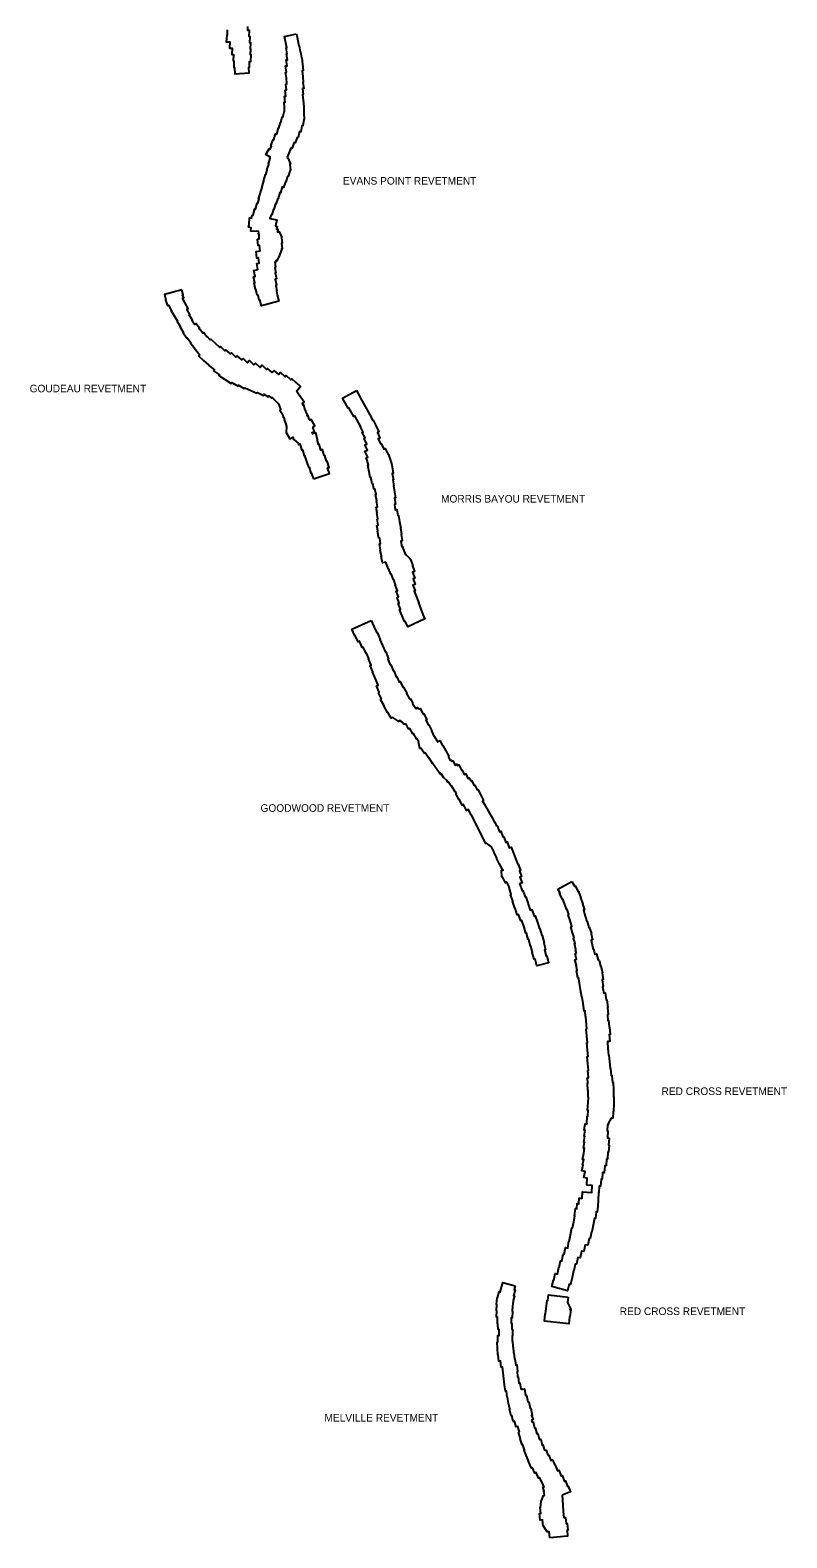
# Model space of a CAD drawing. Extents: x 2650582 to 3923188, y 277893 to 989177.
# Drawn here: x 3143470 to 3159448, y 789511 to 821343 of the extents above; entities that cross this region are included whole.
import ezdxf

# ---------------------------------------------------------------- set-up
doc = ezdxf.new("R2010")
doc.units = 0
doc.layers.add('Level 3', color=7, linetype='Continuous')

msp = doc.modelspace()

# ---------------------------------------------------------------- linework, layer by layer
at = {"layer": 'Level 3'}
for points in [[(3147633, 821352), (3147629, 821238), (3147622, 821239), (3147612, 821099), (3147689, 821094), (3147680, 820964), (3147736, 820960), (3147727, 820830), (3147764, 820828), (3147760, 820694), (3147771, 820693), (3147773, 820558), (3147782, 820558), (3147789, 820424), (3148096, 820440), (3148090, 820564), (3148104, 820564), (3148102, 820682), (3148131, 820681), (3148136, 820821), (3148122, 820821), (3148130, 820942), (3148121, 820943), (3148130, 821073), (3148106, 821074), (3148115, 821204), (3148095, 821206), (3148099, 821335), (3148068, 821336), (3148067, 821422)], [(3148841, 819616), (3148838, 819714), (3148831, 819822), (3148852, 819823), (3148839, 819946), (3148872, 819950), (3148857, 820078), (3148882, 820081), (3148868, 820206), (3148890, 820209), (3148880, 820336), (3148863, 820449), (3148885, 820453), (3148865, 820588), (3148895, 820593), (3148879, 820716), (3148904, 820719), (3148885, 820842), (3148897, 820844), (3148877, 820970), (3148889, 820972), (3148840, 821211), (3149093, 821264)], [(3149093, 821264), (3149145, 821013), (3149153, 821014), (3149173, 820885), (3149179, 820886), (3149199, 820758), (3149205, 820759), (3149223, 820623), (3149219, 820622), (3149238, 820490), (3149214, 820487), (3149231, 820366), (3149226, 820365), (3149236, 820238), (3149231, 820238), (3149246, 820111), (3149224, 820108), (3149238, 819982), (3149223, 819980), (3149236, 819866), (3149246, 819729), (3149248, 819729), (3149251, 819587), (3149253, 819455), (3149247, 819455), (3149228, 819322), (3149210, 819324), (3149184, 819196), (3149157, 819201), (3149126, 819075), (3149106, 819080), (3149069, 818961), (3149044, 818969), (3148996, 818845), (3148973, 818854), (3148929, 818746), (3148932, 818745), (3148894, 818664)], [(3148449, 818289), (3148476, 818389), (3148471, 818391), (3148508, 818510), (3148500, 818512), (3148537, 818641), (3148530, 818644), (3148535, 818663), (3148448, 818715), (3148520, 818834), (3148533, 818826), (3148563, 818890), (3148549, 818896), (3148605, 819032), (3148617, 819028), (3148652, 819154), (3148678, 819147), (3148715, 819279), (3148720, 819277), (3148754, 819394), (3148760, 819392), (3148794, 819510), (3148803, 819508), (3148837, 819618), (3148841, 819616)], [(3148894, 818664), (3148904, 818642), (3148910, 818644), (3148969, 818517), (3148955, 818511), (3148969, 818388), (3148960, 818387), (3148918, 818251), (3148903, 818256), (3148871, 818138), (3148859, 818142)], [(3148300, 817091), (3148131, 817098), (3148134, 817166), (3148081, 817182), (3148096, 817231), (3148105, 817379), (3148142, 817377), (3148161, 817440), (3148176, 817435), (3148216, 817571), (3148231, 817566), (3148266, 817690), (3148275, 817687), (3148303, 817780), (3148295, 817782), (3148369, 818022), (3148364, 818023), (3148402, 818153), (3148397, 818154), (3148439, 818292), (3148449, 818289)], [(3148859, 818142), (3148822, 818023), (3148794, 818032), (3148758, 817909), (3148743, 817913), (3148705, 817790), (3148697, 817792), (3148659, 817669), (3148648, 817673), (3148614, 817561), (3148608, 817563), (3148574, 817441), (3148557, 817445), (3148534, 817367), (3148679, 817336)], [(3148679, 817336), (3148650, 817204), (3148684, 817196), (3148671, 817142), (3148701, 817138), (3148695, 817079), (3148721, 817094), (3148788, 816970), (3148778, 816965), (3148791, 816848), (3148775, 816846), (3148790, 816729), (3148776, 816727), (3148786, 816723), (3148736, 816592), (3148736, 816592), (3148678, 816474), (3148661, 816483), (3148665, 816450), (3148634, 816446), (3148652, 816336), (3148636, 816333), (3148658, 816221), (3148645, 816218), (3148671, 816090), (3148645, 816085), (3148670, 815958), (3148655, 815955), (3148682, 815842), (3148674, 815840), (3148689, 815753), (3148689, 815753), (3148723, 815618), (3148353, 815524), (3148321, 815648), (3148305, 815645), (3148288, 815750), (3148266, 815745), (3148236, 815872), (3148225, 815870), (3148198, 816007), (3148214, 816010), (3148189, 816137), (3148219, 816143), (3148193, 816272), (3148276, 816288), (3148255, 816413), (3148308, 816422), (3148294, 816535), (3148258, 816530), (3148241, 816669), (3148329, 816681), (3148314, 816796), (3148287, 816793), (3148271, 816932), (3148306, 816936), (3148304, 817038), (3148295, 817039), (3148300, 817091)], [(3146676, 815862), (3146304, 815763), (3146335, 815647), (3146327, 815644), (3146369, 815527), (3146388, 815534), (3146453, 815417), (3146450, 815415), (3146583, 815196), (3146577, 815191), (3146645, 815078), (3146639, 815074), (3146711, 814961), (3146698, 814952), (3146781, 814838), (3146789, 814844), (3146864, 814745), (3146855, 814737), (3146934, 814640), (3146930, 814636), (3147018, 814533), (3147012, 814527), (3147052, 814489)], [(3147036, 815039), (3147035, 815040), (3147048, 815051), (3146969, 815153), (3146937, 815129), (3146885, 815212), (3146896, 815219), (3146830, 815331), (3146845, 815340), (3146778, 815452), (3146807, 815469), (3146741, 815576), (3146744, 815578), (3146684, 815685), (3146712, 815695), (3146690, 815754), (3146704, 815758), (3146676, 815862)], [(3149095, 813723), (3149181, 813823), (3149092, 813900), (3149086, 813894), (3148995, 813981), (3148976, 813962), (3148879, 814052), (3148853, 814024), (3148756, 814112), (3148719, 814070), (3148622, 814160), (3148580, 814114), (3148484, 814203), (3148462, 814179), (3148366, 814267), (3148326, 814223), (3148230, 814313), (3148196, 814277), (3148103, 814365), (3148061, 814322), (3147965, 814410), (3147937, 814380), (3147840, 814469), (3147814, 814441), (3147719, 814530), (3147699, 814509), (3147605, 814597), (3147583, 814572), (3147486, 814661), (3147472, 814646), (3147287, 814819), (3147272, 814804), (3147210, 814876), (3147200, 814868), (3147127, 814958), (3147114, 814947), (3147041, 815043), (3147036, 815039)], [(3147052, 814489), (3147029, 814461), (3147133, 814370), (3147130, 814366), (3147245, 814269), (3147243, 814266), (3147360, 814173), (3147344, 814149), (3147466, 814066), (3147456, 814051), (3147713, 813882), (3147727, 813904), (3147859, 813830), (3147867, 813845), (3147992, 813778), (3148000, 813794), (3148260, 813677), (3148268, 813696), (3148396, 813633), (3148407, 813655), (3148499, 813601), (3148512, 813623), (3148563, 813574), (3148576, 813586), (3148596, 813572), (3148672, 813499), (3148712, 813456), (3148713, 813456), (3148758, 813344), (3148758, 813344), (3148762, 813334), (3148740, 813318), (3148799, 813235), (3148816, 813170), (3148825, 813172), (3148841, 813116)], [(3149450, 811869), (3149788, 811985), (3149748, 812100), (3149782, 812111), (3149741, 812245), (3149730, 812241), (3149692, 812366), (3149678, 812361), (3149640, 812486), (3149611, 812477), (3149573, 812601), (3149561, 812597), (3149529, 812703), (3149539, 812706), (3149502, 812841), (3149429, 812821), (3149422, 812850), (3149476, 812874), (3149442, 812949), (3149451, 812952), (3149446, 812972), (3149478, 812988), (3149407, 813123), (3149375, 813106), (3149361, 813133), (3149344, 813197), (3149328, 813193), (3149316, 813215), (3149324, 813219), (3149301, 813263), (3149288, 813312), (3149280, 813310), (3149247, 813430), (3149236, 813427), (3149224, 813465), (3149258, 813489), (3149167, 813619), (3149165, 813617), (3149095, 813723)], [(3150982, 810108), (3150909, 810095), (3150884, 810236), (3150886, 810237), (3150863, 810367), (3150871, 810369), (3150849, 810499), (3150871, 810502), (3150853, 810619), (3150833, 810615), (3150807, 810768), (3150810, 810769), (3150789, 810887), (3150817, 810892), (3150795, 811021), (3150810, 811023), (3150789, 811152), (3150800, 811154), (3150779, 811274), (3150805, 811279), (3150783, 811407), (3150787, 811408), (3150765, 811536), (3150773, 811537), (3150750, 811657), (3150729, 811654), (3150709, 811772), (3150689, 811768), (3150664, 811902), (3150648, 811899), (3150626, 812020), (3150628, 812020), (3150599, 812158), (3150615, 812161), (3150587, 812256), (3150562, 812308), (3150597, 812326), (3150538, 812452), (3150590, 812477), (3150538, 812586), (3150578, 812605), (3150522, 812723), (3150541, 812733), (3150483, 812849), (3150501, 812858), (3150444, 812967), (3150451, 812970), (3150325, 813198), (3150302, 813185), (3150198, 813370), (3150184, 813362), (3150067, 813575), (3150360, 813736)], [(3150360, 813736), (3150476, 813524), (3150472, 813522), (3150643, 813218), (3150645, 813218), (3150708, 813103), (3150715, 813107), (3150779, 812983), (3150774, 812980), (3150832, 812861), (3150802, 812846), (3150857, 812730), (3150822, 812713), (3150871, 812608), (3150885, 812615), (3150940, 812497), (3150966, 812510), (3151029, 812384), (3151039, 812387), (3151076, 812258), (3151086, 812260), (3151115, 812122), (3151113, 812121), (3151138, 811990), (3151117, 811986), (3151142, 811851), (3151126, 811848), (3151147, 811722), (3151142, 811721), (3151166, 811594), (3151161, 811594), (3151183, 811466), (3151163, 811462), (3151185, 811334), (3151160, 811330), (3151180, 811215), (3151213, 811221), (3151233, 811094), (3151245, 811096), (3151267, 810968), (3151271, 810969), (3151295, 810829), (3151290, 810828), (3151312, 810697), (3151305, 810696), (3151325, 810568), (3151323, 810568)], [(3148841, 813116), (3148832, 813111), (3148853, 813071), (3148858, 813052), (3148861, 813053), (3148883, 812972), (3148874, 812850), (3148879, 812850), (3148951, 812712), (3149017, 812747), (3149029, 812704), (3149037, 812706), (3149035, 812704), (3149129, 812622), (3149136, 812598), (3149166, 812606), (3149205, 812478), (3149219, 812482), (3149257, 812358), (3149265, 812361), (3149303, 812236), (3149308, 812238), (3149346, 812113), (3149360, 812118), (3149398, 811993), (3149407, 811996), (3149450, 811869)], [(3151323, 810568), (3151325, 810559), (3151300, 810555), (3151320, 810437), (3151335, 810440), (3151346, 810389), (3151394, 810265), (3151404, 810275), (3151498, 810171), (3151493, 810166), (3151502, 810170), (3151553, 810039), (3151543, 810035), (3151589, 809914), (3151546, 809897), (3151593, 809776), (3151556, 809762), (3151602, 809642), (3151554, 809623), (3151600, 809503), (3151581, 809496), (3151674, 809253), (3151670, 809251), (3151713, 809138), (3151715, 809139), (3151765, 809008), (3151760, 809006), (3151803, 808913), (3151444, 808748), (3151390, 808864), (3151374, 808858), (3151327, 808981), (3151323, 808979), (3151272, 809110), (3151289, 809117), (3151242, 809238), (3151263, 809247), (3151217, 809368), (3151247, 809380), (3151201, 809498), (3151227, 809508), (3151179, 809631), (3151188, 809634), (3151146, 809742), (3151142, 809741), (3151095, 809862), (3151085, 809858), (3151037, 809979), (3151033, 809977), (3150982, 810108)], [(3151402, 806705), (3151389, 806686), (3151374, 806696), (3151358, 806688), (3151343, 806718), (3151268, 806769), (3151252, 806745), (3151125, 806833), (3151096, 806817), (3151023, 806940), (3151018, 806937), (3150939, 807075), (3150944, 807078), (3150871, 807211), (3150892, 807222), (3150824, 807355), (3150841, 807364), (3150780, 807501), (3150817, 807517), (3150762, 807647), (3150759, 807646), (3150700, 807792), (3150705, 807794), (3150653, 807929), (3150669, 807935), (3150613, 808072), (3150619, 808075), (3150570, 808186), (3150563, 808183), (3150503, 808317), (3150482, 808308), (3150421, 808442), (3150397, 808430), (3150336, 808564), (3150324, 808558), (3150264, 808697), (3150671, 808876)], [(3150671, 808876), (3150727, 808749), (3150729, 808750), (3150789, 808620), (3150799, 808624), (3150864, 808480), (3150851, 808475), (3150908, 808349), (3150911, 808351), (3150971, 808213), (3150979, 808217), (3151038, 808072), (3151022, 808065), (3151071, 807940), (3151085, 807946), (3151139, 807810), (3151146, 807813), (3151199, 807688), (3151210, 807693), (3151262, 807578), (3151281, 807588), (3151342, 807469), (3151352, 807475), (3151424, 807344), (3151416, 807339), (3151481, 807226), (3151495, 807234), (3151554, 807134), (3151547, 807129), (3151612, 807021), (3151652, 807044), (3151674, 807006)], [(3151674, 807006), (3151706, 807023), (3151766, 806903), (3151783, 806912), (3151846, 806788), (3151824, 806778), (3151879, 806669), (3151890, 806674)], [(3151675, 806315), (3151633, 806384), (3151631, 806383), (3151564, 806494), (3151552, 806487), (3151485, 806598), (3151474, 806591), (3151469, 806599), (3151458, 806593), (3151402, 806705)], [(3151890, 806674), (3151952, 806549), (3151948, 806547), (3151976, 806486)], [(3152454, 805268), (3152442, 805261), (3152365, 805386), (3152358, 805382), (3152300, 805474), (3152290, 805467), (3152269, 805500), (3152204, 805558), (3152154, 805635), (3152139, 805628), (3152120, 805665), (3152112, 805659), (3151967, 805864), (3151965, 805863), (3151887, 805984), (3151880, 805979), (3151809, 806088), (3151789, 806075), (3151719, 806182), (3151699, 806177), (3151669, 806314), (3151675, 806315)], [(3151976, 806486), (3151990, 806463), (3151987, 806461), (3152049, 806359), (3152047, 806358), (3152072, 806318), (3152118, 806345), (3152179, 806239), (3152182, 806241), (3152310, 806018), (3152294, 806009)], [(3152294, 806009), (3152339, 805920), (3152364, 805932), (3152376, 805905), (3152396, 805915), (3152441, 805826), (3152481, 805845), (3152494, 805818), (3152520, 805832), (3152581, 805717), (3152590, 805721), (3152638, 805629), (3152667, 805643), (3152715, 805545), (3152737, 805558), (3152776, 805490)], [(3152776, 805490), (3152790, 805498), (3152844, 805398), (3152857, 805404), (3152911, 805303), (3152921, 805308), (3152976, 805202), (3152980, 805204), (3153045, 805077), (3153023, 805066), (3153056, 805005)], [(3153267, 803991), (3153212, 804100), (3153105, 804178), (3153092, 804171), (3152912, 804530), (3152911, 804530), (3152790, 804773), (3152784, 804770), (3152724, 804892), (3152685, 804871), (3152623, 804991), (3152595, 804977), (3152534, 805098), (3152526, 805094), (3152461, 805219), (3152475, 805226), (3152454, 805268)], [(3153056, 805005), (3153058, 805006), (3153202, 804745), (3153211, 804749), (3153276, 804617), (3153280, 804619), (3153319, 804537)], [(3153319, 804537), (3153333, 804542), (3153378, 804420), (3153409, 804431), (3153453, 804309), (3153469, 804315), (3153513, 804192), (3153543, 804203), (3153587, 804081), (3153628, 804096), (3153676, 803964), (3153675, 803964), (3153716, 803851), (3153721, 803853), (3153766, 803731), (3153775, 803735), (3153823, 803603), (3153802, 803595), (3153846, 803473), (3153813, 803461), (3153861, 803343), (3153802, 803320)], [(3153592, 803243), (3153534, 803357), (3153507, 803343), (3153446, 803465), (3153429, 803465), (3153424, 803606), (3153461, 803607), (3153454, 803622), (3153447, 803618), (3153388, 803734), (3153384, 803732), (3153317, 803864), (3153325, 803868), (3153262, 803988), (3153267, 803991)], [(3153802, 803320), (3153806, 803311), (3153809, 803312), (3153861, 803174), (3153873, 803178), (3153920, 803042), (3153935, 803047), (3154028, 802766), (3154061, 802778), (3154110, 802637), (3154132, 802645), (3154181, 802504), (3154186, 802505), (3154226, 802366), (3154233, 802368), (3154275, 802226), (3154281, 802227), (3154322, 802075), (3154315, 802073), (3154350, 801930), (3154334, 801926), (3154369, 801794), (3154378, 801796), (3154417, 801651), (3154172, 801585), (3154132, 801732), (3154110, 801726), (3154073, 801868), (3154075, 801868), (3154042, 802001), (3154036, 801999), (3153998, 802144), (3153989, 802142), (3153948, 802281), (3153938, 802278), (3153901, 802406), (3153900, 802406), (3153852, 802545), (3153829, 802538), (3153781, 802675), (3153757, 802668), (3153710, 802808), (3153705, 802806), (3153656, 802955), (3153662, 802957), (3153616, 803089), (3153628, 803094), (3153582, 803240), (3153592, 803243)], [(3155004, 801846), (3154987, 801929), (3154991, 801930), (3154964, 802057), (3154975, 802060), (3154945, 802180), (3154959, 802183), (3154925, 802288), (3154925, 802288), (3154885, 802412), (3154911, 802420), (3154871, 802544), (3154871, 802544), (3154831, 802668), (3154843, 802672), (3154810, 802774), (3154800, 802770), (3154750, 802901), (3154756, 802903), (3154720, 802997), (3154708, 802991), (3154651, 803119), (3154662, 803124), (3154615, 803210), (3154908, 803372)], [(3154908, 803372), (3154970, 803261), (3154988, 803269), (3155041, 803152), (3155048, 803154), (3155098, 803024), (3155091, 803021), (3155137, 802899), (3155131, 802897), (3155173, 802768), (3155152, 802761), (3155192, 802638), (3155187, 802636), (3155224, 802522), (3155230, 802524), (3155270, 802400), (3155277, 802402), (3155320, 802269), (3155314, 802267), (3155347, 802136), (3155319, 802128), (3155347, 801996), (3155345, 801995), (3155357, 801936)], [(3155357, 801936), (3155365, 801938), (3155378, 801888), (3155379, 801888), (3155384, 801863), (3155392, 801834), (3155426, 801843), (3155464, 801707), (3155484, 801711), (3155512, 801583), (3155523, 801586), (3155553, 801437), (3155549, 801437), (3155572, 801298), (3155549, 801294), (3155571, 801149), (3155558, 801147), (3155581, 801012), (3155609, 801017), (3155632, 800870), (3155647, 800872), (3155671, 800708), (3155662, 800706), (3155674, 800559), (3155658, 800557), (3155668, 800437), (3155682, 800438), (3155694, 800295)], [(3155226, 800254), (3155202, 800521), (3155198, 800521), (3155189, 800636), (3155169, 800633), (3155145, 800794), (3155125, 800929), (3155120, 800928), (3155094, 801079), (3155071, 801224), (3155052, 801339), (3155036, 801336), (3155007, 801484), (3155023, 801487), (3154997, 801602), (3155004, 801604), (3154973, 801717), (3155004, 801726), (3154975, 801838), (3155004, 801846)], [(3155694, 800295), (3155701, 800296), (3155715, 800139), (3155695, 800137), (3155707, 799992), (3155658, 799988), (3155671, 799844), (3155667, 799843), (3155680, 799704), (3155689, 799705), (3155702, 799566), (3155703, 799566), (3155717, 799419), (3155725, 799420), (3155738, 799272), (3155753, 799274), (3155767, 799122), (3155782, 799123), (3155786, 798972), (3155790, 798972), (3155789, 798822), (3155796, 798821), (3155793, 798673), (3155796, 798673), (3155788, 798515), (3155779, 798515), (3155771, 798369), (3155736, 798371), (3155676, 798261), (3155674, 798229), (3155660, 798230), (3155652, 798103), (3155670, 798102), (3155660, 797954), (3155693, 797952), (3155684, 797805), (3155695, 797804), (3155685, 797653), (3155669, 797654), (3155659, 797508), (3155643, 797509), (3155633, 797362)], [(3155232, 798246), (3155233, 798250), (3155224, 798251), (3155232, 798415), (3155244, 798415), (3155251, 798542), (3155242, 798543), (3155251, 798701), (3155256, 798700), (3155259, 798816), (3155254, 798816), (3155255, 798955), (3155243, 798955), (3155239, 799107), (3155248, 799107), (3155237, 799226), (3155261, 799229), (3155248, 799378), (3155259, 799379), (3155246, 799517), (3155232, 799673), (3155253, 799676), (3155241, 799806), (3155237, 799805), (3155222, 799963), (3155239, 799964), (3155226, 800109), (3155213, 800252), (3155226, 800254)], [(3155160, 797122), (3155190, 797246), (3155116, 797263), (3155145, 797386), (3155133, 797388), (3155159, 797497), (3155135, 797501), (3155159, 797633), (3155159, 797633), (3155175, 797738), (3155156, 797741), (3155173, 797864), (3155164, 797865), (3155182, 797990), (3155171, 797992), (3155189, 798118), (3155169, 798120), (3155188, 798252), (3155232, 798246)], [(3155633, 797362), (3155603, 797364), (3155593, 797221), (3155555, 797223), (3155546, 797081), (3155524, 797082), (3155515, 796936), (3155485, 796938), (3155476, 796792), (3155472, 796792), (3155463, 796651), (3155454, 796514), (3155444, 796389), (3155422, 796391), (3155405, 796256), (3155387, 796259), (3155361, 796111), (3155358, 796111), (3155333, 795972), (3155322, 795974), (3155296, 795830), (3155275, 795834), (3155246, 795687), (3155187, 795699), (3155159, 795555), (3155115, 795563), (3155087, 795420), (3155034, 795430), (3155005, 795287), (3154979, 795292), (3154952, 795147), (3154942, 795149), (3154912, 795011), (3154882, 794860), (3154851, 794866), (3154816, 794729), (3154486, 794815), (3154522, 794951), (3154526, 794950), (3154556, 795091), (3154606, 795081), (3154635, 795223), (3154643, 795221), (3154669, 795360), (3154696, 795355), (3154724, 795498), (3154748, 795493), (3154776, 795638), (3154820, 795630), (3154846, 795773), (3154855, 795771), (3154882, 795908), (3154909, 796059), (3154925, 796056), (3154948, 796186), (3154947, 796187), (3154969, 796312), (3154966, 796312), (3154985, 796464), (3155011, 796461), (3155021, 796567), (3155059, 796564), (3155066, 796685), (3155127, 796681), (3155136, 796818), (3155327, 796805), (3155335, 796947), (3155226, 796954), (3155235, 797106), (3155160, 797122)], [(3153803, 791741), (3153771, 791863), (3153733, 791852), (3153697, 791974), (3153667, 791967), (3153638, 792093), (3153625, 792089), (3153591, 792229), (3153596, 792230), (3153570, 792354), (3153550, 792480), (3153545, 792480), (3153529, 792611), (3153505, 792608), (3153488, 792739), (3153485, 792739), (3153441, 793119), (3153419, 793116), (3153403, 793246), (3153366, 793241), (3153349, 793374), (3153346, 793374), (3153335, 793518), (3153339, 793518), (3153332, 793646), (3153347, 793647), (3153345, 793785), (3153373, 793785), (3153371, 793907), (3153349, 793907), (3153347, 794033), (3153339, 794033), (3153339, 794170), (3153316, 794171), (3153324, 794302), (3153319, 794302), (3153327, 794437), (3153319, 794438), (3153333, 794579), (3153337, 794578), (3153373, 794708), (3153396, 794701), (3153451, 794901), (3153710, 794830)], [(3153710, 794830), (3153690, 794756), (3153712, 794750), (3153677, 794624), (3153697, 794618), (3153671, 794523), (3153667, 794511), (3153657, 794404), (3153655, 794404), (3153649, 794299), (3153656, 794299), (3153648, 794153), (3153624, 794154), (3153624, 794046), (3153640, 794046), (3153643, 793917), (3153652, 793917), (3153656, 793776), (3153650, 793776), (3153651, 793664), (3153654, 793664), (3153661, 793544), (3153668, 793545), (3153678, 793415), (3153683, 793415), (3153699, 793293), (3153706, 793293), (3153722, 793160), (3153744, 793162), (3153759, 793025), (3153751, 793024), (3153763, 792913), (3153772, 792913), (3153787, 792779), (3153813, 792783), (3153830, 792656), (3153853, 792659), (3153854, 792646)], [(3154830, 794595), (3154818, 794482), (3154884, 794339), (3154869, 794332), (3154884, 794330), (3154869, 794174), (3154860, 794175), (3154845, 794031), (3154331, 794084), (3154347, 794240), (3154355, 794239), (3154384, 794525), (3154400, 794524), (3154413, 794640), (3154830, 794595)], [(3153854, 792646), (3153905, 792655), (3153932, 792517), (3153952, 792521), (3153979, 792382), (3153997, 792386), (3154026, 792247), (3154039, 792250), (3154068, 792096), (3154059, 792094), (3154092, 792008), (3154058, 791995)], [(3154058, 791995), (3154070, 791953), (3154089, 791958), (3154122, 791831), (3154135, 791834), (3154170, 791707), (3154190, 791712), (3154218, 791603), (3154220, 791604), (3154226, 791587), (3154250, 791593), (3154276, 791493), (3154285, 791469), (3154296, 791472), (3154324, 791382), (3154326, 791383), (3154335, 791359), (3154365, 791363), (3154401, 791254)], [(3154230, 790783), (3154206, 790773), (3154157, 790893), (3154124, 790878), (3154076, 790987), (3154058, 790980), (3154003, 791109), (3154003, 791109), (3153955, 791232), (3153951, 791230), (3153904, 791369), (3153910, 791371), (3153874, 791477), (3153861, 791473), (3153817, 791605), (3153821, 791607), (3153781, 791734), (3153803, 791741)], [(3154401, 791254), (3154420, 791260), (3154461, 791142), (3154502, 791157), (3154546, 791043), (3154556, 791047), (3154603, 790926), (3154634, 790937), (3154680, 790815), (3154703, 790824), (3154750, 790704), (3154773, 790713), (3154819, 790598), (3154830, 790602), (3154879, 790486), (3154701, 790411)], [(3154440, 789511), (3154429, 789641), (3154392, 789637), (3154386, 789639), (3154309, 789756), (3154316, 789761), (3154304, 789760), (3154292, 789889), (3154237, 789885), (3154225, 790024), (3154251, 790027), (3154239, 790156), (3154244, 790155), (3154262, 790281), (3154258, 790282), (3154310, 790404), (3154317, 790401), (3154316, 790408), (3154332, 790409), (3154316, 790496), (3154322, 790497), (3154298, 790584), (3154321, 790590), (3154302, 790631), (3154305, 790633), (3154252, 790734), (3154247, 790732), (3154230, 790783)], [(3154701, 790411), (3154718, 790198), (3154728, 790068), (3154739, 789939), (3154777, 789942), (3154790, 789813), (3154810, 789814), (3154822, 789675), (3154807, 789674), (3154818, 789544), (3154440, 789511)]]:
    msp.add_lwpolyline(points, dxfattribs=at)

# ---------------------------------------------------------------- texts
for s, p in [('EVANS POINT REVETMENT', (3150075, 818082)), ('GOUDEAU REVETMENT', (3143459, 813697)), ('MORRIS BAYOU REVETMENT', (3152146, 811369)), ('GOODWOOD REVETMENT', (3148335, 804840)), ('RED CROSS REVETMENT', (3156802, 798861)), ('RED CROSS REVETMENT', (3155919, 794215)), ('MELVILLE REVETMENT', (3149685, 791966))]:
    msp.add_text(s, height=160, dxfattribs=at).set_placement(p)

doc.saveas('drawing.dxf')
